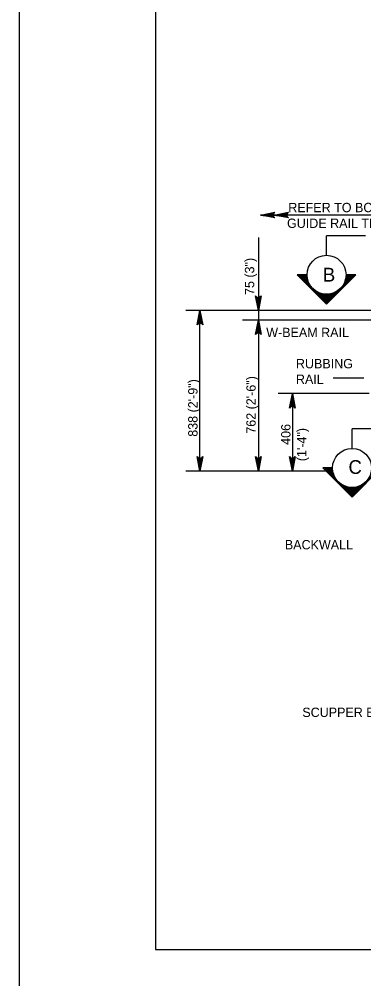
# Model space of a CAD drawing. Extents: x 0 to 36.3, y -66 to 0.
# Drawn here: x 0 to 4.42, y -21.62 to -9.31 of the extents above; entities that cross this region are included whole.
import ezdxf

# ---------------------------------------------------------------- set-up
doc = ezdxf.new("R2010")
doc.units = 0
for name, color, linetype in [('1', 7, 'Continuous'), ('3', 7, 'Continuous'), ('63', 7, 'Continuous')]:
    doc.layers.add(name, color=color, linetype=linetype)

msp = doc.modelspace()

# ---------------------------------------------------------------- linework, layer by layer
at = {"layer": '1'}
msp.add_lwpolyline([(1.75, -21.25), (33.25, -21.25), (33.25, -0.75), (1.75, -0.75)], close=True, dxfattribs=at)
at = {"layer": '3'}
for p, q in [((6.579, -11.825), (3.093, -11.825)), ((3.067, -12.114), (3.067, -13.049)), ((4.441, -12.092), (3.941, -12.092)), ((3.941, -12.342), (3.941, -12.092)), ((3.941, -12.967), (3.566, -12.592)), ((3.691, -12.592), (3.566, -12.592)), ((3.573, -12.599), (3.58, -12.592)), ((3.58, -12.606), (3.595, -12.592)), ((3.587, -12.613), (3.609, -12.592)), ((3.594, -12.62), (3.623, -12.592)), ((3.601, -12.628), (3.637, -12.592)), ((3.609, -12.635), (3.651, -12.592)), ((3.616, -12.642), (3.665, -12.592)), ((3.623, -12.649), (3.679, -12.592)), ((3.63, -12.656), (3.691, -12.595)), ((3.637, -12.663), (3.691, -12.608)), ((3.644, -12.67), (3.693, -12.621)), ((3.651, -12.677), (3.695, -12.633)), ((3.658, -12.684), (3.697, -12.646)), ((3.665, -12.691), (3.7, -12.657)), ((3.672, -12.698), (3.703, -12.668)), ((3.679, -12.705), (3.706, -12.678)), ((3.934, -12.96), (4.302, -12.592)), ((3.941, -12.967), (4.316, -12.592)), ((4.149, -12.731), (4.288, -12.592)), ((4.167, -12.698), (4.274, -12.592)), ((4.177, -12.674), (4.259, -12.592)), ((4.183, -12.654), (4.245, -12.592)), ((4.187, -12.636), (4.231, -12.592)), ((4.189, -12.62), (4.217, -12.592)), ((4.191, -12.604), (4.203, -12.592)), ((4.316, -12.592), (4.191, -12.592)), ((3.686, -12.712), (3.71, -12.688)), ((3.693, -12.72), (3.715, -12.698)), ((3.7, -12.727), (3.719, -12.708)), ((3.708, -12.734), (3.724, -12.717)), ((3.715, -12.741), (3.73, -12.726)), ((3.722, -12.748), (3.735, -12.734)), ((3.729, -12.755), (3.741, -12.742)), ((3.736, -12.762), (3.747, -12.75)), ((3.743, -12.769), (3.754, -12.758)), ((3.75, -12.776), (3.761, -12.765)), ((3.757, -12.783), (3.768, -12.772)), ((3.764, -12.79), (3.775, -12.779)), ((3.771, -12.797), (3.783, -12.786)), ((3.778, -12.804), (3.791, -12.792)), ((3.785, -12.811), (3.799, -12.798)), ((3.792, -12.819), (3.807, -12.803)), ((3.927, -12.953), (4.08, -12.8)), ((3.799, -12.826), (3.816, -12.809)), ((3.807, -12.833), (3.825, -12.814)), ((3.814, -12.84), (3.835, -12.818)), ((3.821, -12.847), (3.845, -12.823)), ((3.828, -12.854), (3.855, -12.827)), ((3.835, -12.861), (3.865, -12.83)), ((3.842, -12.868), (3.876, -12.833)), ((3.849, -12.875), (3.888, -12.836)), ((3.856, -12.882), (3.9, -12.839)), ((3.863, -12.889), (3.912, -12.84)), ((3.87, -12.896), (3.925, -12.841)), ((3.877, -12.903), (3.939, -12.842)), ((3.884, -12.91), (3.953, -12.842)), ((3.891, -12.918), (3.968, -12.84)), ((3.898, -12.925), (3.985, -12.838)), ((3.905, -12.932), (4.003, -12.834)), ((3.913, -12.939), (4.023, -12.828)), ((3.92, -12.946), (4.047, -12.818)), ((7.102, -13.049), (2.138, -13.049)), ((2.318, -15.111), (2.318, -13.049)), ((3.067, -13.049), (3.067, -15.111)), ((4.532, -13.174), (2.865, -13.174)), ((4.419, -13.918), (4.028, -13.918)), ((4.487, -14.116), (3.323, -14.116)), ((3.503, -14.116), (3.503, -15.111)), ((4.269, -14.819), (4.269, -14.569)), ((4.769, -14.569), (4.269, -14.569)), ((3.977, -15.111), (2.138, -15.111)), ((3.496, -15.111), (3.323, -15.111)), ((4.269, -15.444), (3.894, -15.069)), ((4.019, -15.069), (3.894, -15.069)), ((3.915, -15.091), (3.937, -15.069)), ((3.922, -15.098), (3.951, -15.069)), ((3.929, -15.105), (3.965, -15.069)), ((3.937, -15.112), (3.979, -15.069)), ((3.944, -15.119), (3.993, -15.069)), ((3.951, -15.126), (4.008, -15.069)), ((3.958, -15.133), (4.019, -15.072)), ((3.965, -15.14), (4.019, -15.086)), ((3.972, -15.147), (4.021, -15.099)), ((3.979, -15.155), (4.023, -15.111)), ((3.986, -15.162), (4.025, -15.123)), ((3.993, -15.169), (4.027, -15.134)), ((4.262, -15.437), (4.63, -15.069)), ((4.269, -15.444), (4.644, -15.069)), ((4, -15.176), (4.031, -15.145)), ((4.007, -15.183), (4.034, -15.156)), ((4.014, -15.19), (4.038, -15.166)), ((4.021, -15.197), (4.043, -15.176)), ((4.029, -15.204), (4.047, -15.185)), ((4.036, -15.211), (4.052, -15.194)), ((4.043, -15.218), (4.058, -15.203)), ((4.05, -15.225), (4.063, -15.212)), ((4.057, -15.232), (4.069, -15.22)), ((4.064, -15.239), (4.075, -15.228)), ((4.071, -15.246), (4.082, -15.236)), ((4.078, -15.254), (4.089, -15.243)), ((4.085, -15.261), (4.096, -15.25)), ((4.092, -15.268), (4.103, -15.257)), ((4.099, -15.275), (4.111, -15.263)), ((4.106, -15.282), (4.119, -15.269)), ((4.113, -15.289), (4.127, -15.275)), ((4.12, -15.296), (4.135, -15.281)), ((4.127, -15.303), (4.144, -15.286)), ((4.135, -15.31), (4.154, -15.291)), ((4.142, -15.317), (4.163, -15.296)), ((4.149, -15.324), (4.173, -15.3)), ((4.156, -15.331), (4.183, -15.304)), ((4.163, -15.338), (4.193, -15.308)), ((4.17, -15.345), (4.204, -15.311)), ((4.177, -15.353), (4.216, -15.314)), ((4.184, -15.36), (4.228, -15.316)), ((4.191, -15.367), (4.24, -15.318)), ((4.198, -15.374), (4.253, -15.319)), ((4.205, -15.381), (4.267, -15.319)), ((4.212, -15.388), (4.281, -15.319)), ((4.219, -15.395), (4.296, -15.318)), ((4.226, -15.402), (4.313, -15.316)), ((4.234, -15.409), (4.331, -15.312)), ((4.241, -15.416), (4.351, -15.306)), ((4.248, -15.423), (4.375, -15.296)), ((4.255, -15.43), (4.408, -15.277))]:
    msp.add_line(p, q, dxfattribs=at)
for points in [[(3.093, -11.825), (3.28, -11.79), (3.265, -11.8), (3.258, -11.813), (3.256, -11.825), (3.258, -11.838), (3.265, -11.85), (3.28, -11.86), (3.093, -11.825), (3.265, -11.85), (3.258, -11.838), (3.093, -11.825), (3.256, -11.825), (3.258, -11.813), (3.093, -11.825), (3.265, -11.8)], [(3.267, -11.825), (3.454, -11.79), (3.439, -11.8), (3.432, -11.813), (3.43, -11.825), (3.432, -11.838), (3.439, -11.85), (3.454, -11.86), (3.267, -11.825), (3.439, -11.85), (3.432, -11.838), (3.267, -11.825), (3.43, -11.825), (3.432, -11.813), (3.267, -11.825), (3.439, -11.8)], [(3.067, -13.049), (3.032, -12.862), (3.042, -12.877), (3.054, -12.884), (3.067, -12.886), (3.079, -12.884), (3.092, -12.877), (3.102, -12.862), (3.067, -13.049), (3.092, -12.877), (3.079, -12.884), (3.067, -13.049), (3.067, -12.886), (3.054, -12.884), (3.067, -13.049), (3.042, -12.877)], [(2.318, -13.049), (2.353, -13.235), (2.343, -13.221), (2.331, -13.213), (2.318, -13.211), (2.306, -13.213), (2.293, -13.221), (2.283, -13.235), (2.318, -13.049), (2.293, -13.221), (2.306, -13.213), (2.318, -13.049), (2.318, -13.211), (2.331, -13.213), (2.318, -13.049), (2.343, -13.221)], [(3.067, -13.174), (3.102, -13.36), (3.092, -13.346), (3.079, -13.338), (3.067, -13.336), (3.054, -13.338), (3.042, -13.346), (3.032, -13.36), (3.067, -13.174), (3.042, -13.346), (3.054, -13.338), (3.067, -13.174), (3.067, -13.336), (3.079, -13.338), (3.067, -13.174), (3.092, -13.346)], [(3.503, -14.116), (3.538, -14.302), (3.528, -14.288), (3.516, -14.281), (3.503, -14.278), (3.491, -14.281), (3.478, -14.288), (3.468, -14.302), (3.503, -14.116), (3.478, -14.288), (3.491, -14.281), (3.503, -14.116), (3.503, -14.278), (3.516, -14.281), (3.503, -14.116), (3.528, -14.288)], [(2.318, -15.111), (2.283, -14.925), (2.293, -14.939), (2.306, -14.946), (2.318, -14.948), (2.331, -14.946), (2.343, -14.939), (2.353, -14.925), (2.318, -15.111), (2.343, -14.939), (2.331, -14.946), (2.318, -15.111), (2.318, -14.948), (2.306, -14.946), (2.318, -15.111), (2.293, -14.939)], [(3.067, -15.111), (3.032, -14.925), (3.042, -14.939), (3.054, -14.946), (3.067, -14.948), (3.079, -14.946), (3.092, -14.939), (3.102, -14.925), (3.067, -15.111), (3.092, -14.939), (3.079, -14.946), (3.067, -15.111), (3.067, -14.948), (3.054, -14.946), (3.067, -15.111), (3.042, -14.939)], [(3.503, -15.111), (3.468, -14.925), (3.478, -14.939), (3.491, -14.946), (3.503, -14.948), (3.516, -14.946), (3.528, -14.939), (3.538, -14.925), (3.503, -15.111), (3.528, -14.939), (3.516, -14.946), (3.503, -15.111), (3.503, -14.948), (3.491, -14.946), (3.503, -15.111), (3.478, -14.939)]]:
    msp.add_lwpolyline(points, dxfattribs=at)
for points in [[(3.088, -12.927), (3.046, -12.927), (3.067, -13.052)], [(2.297, -13.174), (2.339, -13.174), (2.318, -13.049)], [(3.088, -13.299), (3.046, -13.299), (3.067, -13.174)], [(3.483, -14.236), (3.523, -14.236), (3.503, -14.116)], [(2.297, -14.986), (2.339, -14.986), (2.318, -15.111)], [(3.046, -14.986), (3.088, -14.986), (3.067, -15.111)], [(3.483, -14.991), (3.523, -14.991), (3.503, -15.111)]]:
    msp.add_lwpolyline(points, close=True, dxfattribs=at)
for centre in [(3.941, -12.592), (4.269, -15.07)]:
    msp.add_circle(centre, 0.25, dxfattribs=at)
at = {"layer": '63'}
msp.add_lwpolyline([(0, -22), (34, -22), (34, 0), (0, 0)], close=True, dxfattribs=at)

# ---------------------------------------------------------------- texts
at = {"layer": '3'}
for s, height, p in [('   REFER TO BC-739M FOR', 0.12, (3.317, -11.789)), ('   GUIDE RAIL TRANSITION.', 0.12, (3.301, -11.991)), ('B', 0.177, (3.895, -12.679)), ('W-BEAM RAIL', 0.12, (3.168, -13.392)), ('RUBBING', 0.12, (3.549, -13.792)), ('RAIL', 0.12, (3.549, -13.992)), ('C', 0.177, (4.223, -15.147)), ('BACKWALL', 0.12, (3.407, -16.115)), ('SCUPPER BLOCK (SHOWN BEYOND)', 0.12, (3.631, -18.266))]:
    msp.add_text(s, height=height, dxfattribs=at).set_placement(p)
for s, p in [('75 (3")', (3.014, -12.851)), ('762 (2\'-6")', (3.033, -14.631)), ('838 (2\'-9")', (2.287, -14.67)), ('406', (3.479, -14.774)), ('(1\'-4")', (3.682, -14.984))]:
    msp.add_text(s, height=0.12, rotation=90, dxfattribs=at).set_placement(p)

doc.saveas('drawing.dxf')
